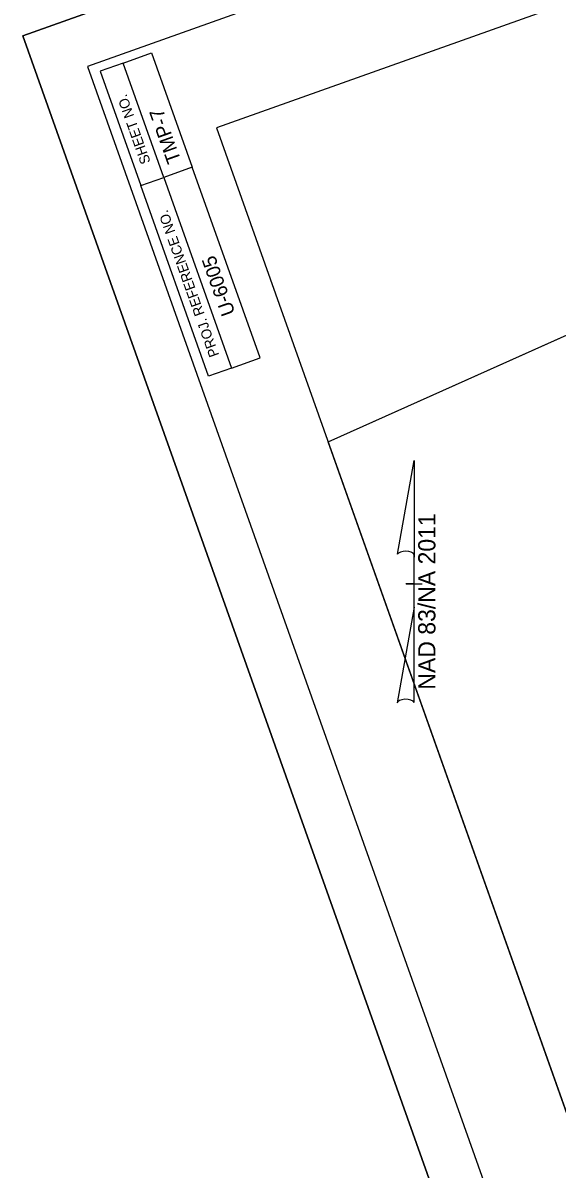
# Model space of a CAD drawing. Extents: x 1615843 to 1618439, y 899470 to 903922.
# Drawn here: x 1615843 to 1616107, y 902993 to 903560 of the extents above; entities that cross this region are included whole.
import ezdxf

# ---------------------------------------------------------------- set-up
doc = ezdxf.new("R2010")
doc.units = 0
for name, color, linetype in [('DEV BORDER CELL', 7, 'Continuous'), ('Matchline', 7, 'Continuous'), ('Prop North Arrow NAD83 for Plan Sheets CELL', 7, 'Continuous'), ('Scratch_Level_0', 7, 'Continuous'), ('Scratch_Level_5', 7, 'Continuous'), ('Sheet Plot Border Outside CELL', 7, 'Continuous')]:
    doc.layers.add(name, color=color, linetype=linetype)

msp = doc.modelspace()

# ---------------------------------------------------------------- linework, layer by layer
at = {"layer": 'DEV BORDER CELL'}
msp.add_line((1615912.58, 903483.23), (1615892.48, 903539.76), dxfattribs=at)
for points in [[(1615874.87, 903538.12), (1616377.33, 902124.77), (1617366.67, 902476.49), (1616864.22, 903889.84)], [(1615912.58, 903483.23), (1615892.48, 903539.76), (1615906.62, 903544.78), (1615926.71, 903488.25)], [(1615912.58, 903483.23), (1615892.48, 903539.76), (1615881.18, 903535.74), (1615901.27, 903479.21)], [(1615912.58, 903483.23), (1615946.08, 903389), (1615960.21, 903394.03), (1615926.71, 903488.25)], [(1615934.77, 903384.98), (1615901.27, 903479.21), (1615912.58, 903483.23), (1615946.08, 903389)]]:
    msp.add_lwpolyline(points, close=True, dxfattribs=at)
at = {"layer": 'Matchline'}
msp.add_line((1615993.9, 903352.57), (1616672.62, 903656.48), dxfattribs=at)
at = {"layer": 'Prop North Arrow NAD83 for Plan Sheets CELL'}
for p, q in [((1616028.19, 903296.98), (1616036.39, 903343.33)), ((1616036.44, 903343.33), (1616036.39, 903343.33)), ((1616036.44, 903343.33), (1616036.39, 903343.33)), ((1616036.44, 903343.33), (1616036.44, 903295.53)), ((1616036.44, 903270.73), (1616036.44, 903296.93)), ((1616036.44, 903295.53), (1616036.44, 903296.88)), ((1616032.44, 903282.33), (1616032.39, 903282.33)), ((1616035.99, 903282.33), (1616032.44, 903282.33)), ((1616032.49, 903282.33), (1616040.49, 903282.33)), ((1616036.44, 903270.73), (1616028.09, 903223.48)), ((1616036.49, 903223.68), (1616036.44, 903270.73))]:
    msp.add_line(p, q, dxfattribs=at)
for centre, start_param, end_param in [((1616032.33, 903296.48), 0.216388, 2.908219), ((1616032.33, 903223.31), 0.201328, 3.141593)]:
    msp.add_ellipse(centre, major_axis=(4.23, -0.03), ratio=0.461098, start_param=start_param, end_param=end_param, dxfattribs=at)
at = {"layer": 'Scratch_Level_0'}
msp.add_lwpolyline([(1615938.73, 903507.75), (1616407.69, 902188.63), (1617302.81, 902506.85), (1617008.42, 903334.93), (1616896.98, 903295.32), (1616722.42, 903786.36)], close=True, dxfattribs=at)
at = {"layer": 'Scratch_Level_5'}
msp.add_lwpolyline([(1616347.43, 902358.15), (1615993.9, 903352.57), (1616755.41, 903693.55), (1617118.27, 903131.4), (1617302.81, 902506.85), (1616959.09, 902384.66)], close=True, dxfattribs=at)
at = {"layer": 'Sheet Plot Border Outside CELL'}
for points in [[(1617444.82, 902331.28), (1616879.4, 903921.77), (1615842.94, 903553.3), (1616408.37, 901962.82)], [(1617444.82, 902331.28), (1616408.37, 901962.82), (1615842.94, 903553.3), (1616879.4, 903921.77)]]:
    msp.add_lwpolyline(points, close=True, dxfattribs=at)

# ---------------------------------------------------------------- texts
at = {"layer": 'DEV BORDER CELL'}
for s, height, rotation, p in [('SHEET NO.', 4.999, 109.5712, (1615906.16, 903490.85)), ('TMP-7', 7, 109.5707, (1615921.27, 903491.62)), ('PROJ. REFERENCE NO.', 4.9992, 109.5712, (1615940.06, 903395.47)), ('U-6005', 7, 109.5707, (1615948.07, 903416.24))]:
    msp.add_text(s, height=height, rotation=rotation, dxfattribs=at).set_placement(p)
at = {"layer": 'Prop North Arrow NAD83 for Plan Sheets CELL'}
msp.add_text('NAD 83/NA 2011', height=8.5, rotation=90, dxfattribs=at).set_placement((1616046.96, 903230.02))

doc.saveas('drawing.dxf')
